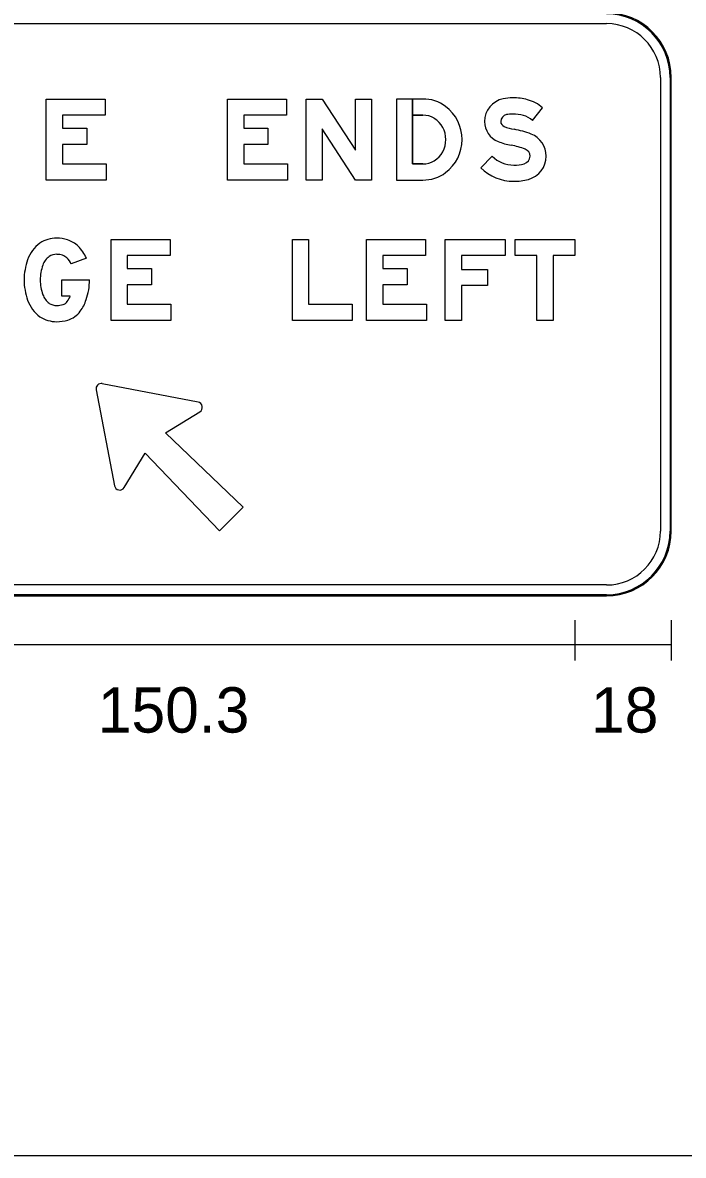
# Model space of a CAD drawing. Extents: x 10268147 to 10268469, y 2141099 to 2141204.
# Drawn here: x 10268201.56 to 10268211.77, y 2141130.4 to 2141147.88 of the extents above; entities that cross this region are included whole.
import ezdxf

# ---------------------------------------------------------------- set-up
doc = ezdxf.new("R2010")
doc.units = 0
for name, color, linetype in [('61', 7, 'Continuous'), ('GSDims', 7, 'Continuous'), ('PlotBorder_dp', 7, 'Continuous')]:
    doc.layers.add(name, color=color, linetype=linetype)

msp = doc.modelspace()

# ---------------------------------------------------------------- linework, layer by layer
at = {"layer": '61'}
msp.add_line((10268153.875, 2141130.399), (10268229.209, 2141130.399), dxfattribs=at)
at = {"layer": 'GSDims'}
for p, q in [((10268210.093, 2141138.662), (10268210.093, 2141138.037)), ((10268210.093, 2141138.662), (10268210.093, 2141138.037)), ((10268211.581, 2141138.662), (10268211.581, 2141138.037)), ((10268197.568, 2141138.287), (10268210.093, 2141138.287)), ((10268210.093, 2141138.287), (10268211.581, 2141138.287))]:
    msp.add_line(p, q, dxfattribs=at)
at = {"layer": 'PlotBorder_dp'}
for p, q in [((10268197.081, 2141147.87), (10268210.581, 2141147.87)), ((10268197.081, 2141147.87), (10268210.581, 2141147.87)), ((10268211.414, 2141147.037), (10268211.414, 2141140.037)), ((10268211.414, 2141147.037), (10268211.414, 2141140.037)), ((10268211.564, 2141147.037), (10268211.564, 2141140.037)), ((10268211.581, 2141140.037), (10268211.581, 2141147.037)), ((10268211.581, 2141140.037), (10268211.581, 2141147.037)), ((10268211.581, 2141140.037), (10268211.581, 2141147.037)), ((10268211.581, 2141140.037), (10268211.581, 2141147.037)), ((10268207.745, 2141145.705), (10268207.585, 2141145.705)), ((10268207.745, 2141145.705), (10268207.585, 2141145.705)), ((10268207.745, 2141145.705), (10268207.745, 2141145.705)), ((10268207.745, 2141145.455), (10268207.745, 2141145.455)), ((10268204.272, 2141142.027), (10268202.792, 2141142.311)), ((10268204.272, 2141142.027), (10268202.792, 2141142.311)), ((10268204.272, 2141142.027), (10268202.792, 2141142.311)), ((10268202.696, 2141142.215), (10268202.981, 2141140.736)), ((10268202.696, 2141142.215), (10268202.981, 2141140.736)), ((10268202.696, 2141142.215), (10268202.981, 2141140.736)), ((10268202.981, 2141140.736), (10268202.981, 2141140.736)), ((10268202.981, 2141140.736), (10268202.981, 2141140.736)), ((10268202.981, 2141140.736), (10268202.981, 2141140.736)), ((10268210.581, 2141139.204), (10268197.082, 2141139.204)), ((10268210.581, 2141139.204), (10268197.082, 2141139.204)), ((10268210.581, 2141139.054), (10268197.081, 2141139.054)), ((10268197.081, 2141139.037), (10268210.581, 2141139.037)), ((10268197.081, 2141139.037), (10268210.581, 2141139.037)), ((10268197.082, 2141139.037), (10268210.581, 2141139.037)), ((10268197.082, 2141139.037), (10268210.581, 2141139.037))]:
    msp.add_line(p, q, dxfattribs=at)
for points in [[(10268202.838, 2141146.705), (10268202.838, 2141146.455), (10268202.176, 2141146.455), (10268202.176, 2141146.255), (10268202.551, 2141146.255), (10268202.551, 2141146.005), (10268202.176, 2141146.005), (10268202.176, 2141145.705), (10268202.851, 2141145.705), (10268202.851, 2141145.455), (10268201.926, 2141145.455), (10268201.926, 2141146.705)], [(10268202.838, 2141146.705), (10268202.838, 2141146.455), (10268202.176, 2141146.455), (10268202.176, 2141146.255), (10268202.551, 2141146.255), (10268202.551, 2141146.005), (10268202.176, 2141146.005), (10268202.176, 2141145.705), (10268202.851, 2141145.705), (10268202.851, 2141145.455), (10268201.926, 2141145.455), (10268201.926, 2141146.705)], [(10268202.838, 2141146.705), (10268202.838, 2141146.455), (10268202.176, 2141146.455), (10268202.176, 2141146.255), (10268202.551, 2141146.255), (10268202.551, 2141146.005), (10268202.176, 2141146.005), (10268202.176, 2141145.705), (10268202.851, 2141145.705), (10268202.851, 2141145.455), (10268201.926, 2141145.455), (10268201.926, 2141146.705)], [(10268205.638, 2141146.705), (10268205.638, 2141146.455), (10268204.976, 2141146.455), (10268204.976, 2141146.255), (10268205.351, 2141146.255), (10268205.351, 2141146.005), (10268204.976, 2141146.005), (10268204.976, 2141145.705), (10268205.651, 2141145.705), (10268205.651, 2141145.455), (10268204.726, 2141145.455), (10268204.726, 2141146.705)], [(10268205.638, 2141146.705), (10268205.638, 2141146.455), (10268204.976, 2141146.455), (10268204.976, 2141146.255), (10268205.351, 2141146.255), (10268205.351, 2141146.005), (10268204.976, 2141146.005), (10268204.976, 2141145.705), (10268205.651, 2141145.705), (10268205.651, 2141145.455), (10268204.726, 2141145.455), (10268204.726, 2141146.705)], [(10268205.638, 2141146.705), (10268205.638, 2141146.455), (10268204.976, 2141146.455), (10268204.976, 2141146.255), (10268205.351, 2141146.255), (10268205.351, 2141146.005), (10268204.976, 2141146.005), (10268204.976, 2141145.705), (10268205.651, 2141145.705), (10268205.651, 2141145.455), (10268204.726, 2141145.455), (10268204.726, 2141146.705)], [(10268205.939, 2141146.705), (10268206.189, 2141146.705), (10268206.702, 2141145.917), (10268206.702, 2141146.705), (10268206.952, 2141146.705), (10268206.952, 2141145.455), (10268206.705, 2141145.455), (10268206.189, 2141146.246), (10268206.189, 2141145.455), (10268205.939, 2141145.455)], [(10268205.939, 2141146.705), (10268206.189, 2141146.705), (10268206.702, 2141145.917), (10268206.702, 2141146.705), (10268206.952, 2141146.705), (10268206.952, 2141145.455), (10268206.705, 2141145.455), (10268206.189, 2141146.246), (10268206.189, 2141145.455), (10268205.939, 2141145.455)], [(10268205.939, 2141146.705), (10268206.189, 2141146.705), (10268206.702, 2141145.917), (10268206.702, 2141146.705), (10268206.952, 2141146.705), (10268206.952, 2141145.455), (10268206.705, 2141145.455), (10268206.189, 2141146.246), (10268206.189, 2141145.455), (10268205.939, 2141145.455)], [(10268203.84, 2141144.538), (10268203.84, 2141144.288), (10268203.178, 2141144.288), (10268203.178, 2141144.088), (10268203.553, 2141144.088), (10268203.553, 2141143.838), (10268203.178, 2141143.838), (10268203.178, 2141143.538), (10268203.853, 2141143.538), (10268203.853, 2141143.288), (10268202.928, 2141143.288), (10268202.928, 2141144.538)], [(10268203.84, 2141144.538), (10268203.84, 2141144.288), (10268203.178, 2141144.288), (10268203.178, 2141144.088), (10268203.553, 2141144.088), (10268203.553, 2141143.838), (10268203.178, 2141143.838), (10268203.178, 2141143.538), (10268203.853, 2141143.538), (10268203.853, 2141143.288), (10268202.928, 2141143.288), (10268202.928, 2141144.538)], [(10268203.84, 2141144.538), (10268203.84, 2141144.288), (10268203.178, 2141144.288), (10268203.178, 2141144.088), (10268203.553, 2141144.088), (10268203.553, 2141143.838), (10268203.178, 2141143.838), (10268203.178, 2141143.538), (10268203.853, 2141143.538), (10268203.853, 2141143.288), (10268202.928, 2141143.288), (10268202.928, 2141144.538)], [(10268205.978, 2141143.538), (10268206.653, 2141143.538), (10268206.653, 2141143.288), (10268205.728, 2141143.288), (10268205.728, 2141144.538), (10268205.978, 2141144.538)], [(10268205.978, 2141143.538), (10268206.653, 2141143.538), (10268206.653, 2141143.288), (10268205.728, 2141143.288), (10268205.728, 2141144.538), (10268205.978, 2141144.538)], [(10268205.978, 2141143.538), (10268206.653, 2141143.538), (10268206.653, 2141143.288), (10268205.728, 2141143.288), (10268205.728, 2141144.538), (10268205.978, 2141144.538)], [(10268207.787, 2141144.538), (10268207.787, 2141144.288), (10268207.125, 2141144.288), (10268207.125, 2141144.088), (10268207.5, 2141144.088), (10268207.5, 2141143.838), (10268207.125, 2141143.838), (10268207.125, 2141143.538), (10268207.8, 2141143.538), (10268207.8, 2141143.288), (10268206.875, 2141143.288), (10268206.875, 2141144.538)], [(10268207.787, 2141144.538), (10268207.787, 2141144.288), (10268207.125, 2141144.288), (10268207.125, 2141144.088), (10268207.5, 2141144.088), (10268207.5, 2141143.838), (10268207.125, 2141143.838), (10268207.125, 2141143.538), (10268207.8, 2141143.538), (10268207.8, 2141143.288), (10268206.875, 2141143.288), (10268206.875, 2141144.538)], [(10268207.787, 2141144.538), (10268207.787, 2141144.288), (10268207.125, 2141144.288), (10268207.125, 2141144.088), (10268207.5, 2141144.088), (10268207.5, 2141143.838), (10268207.125, 2141143.838), (10268207.125, 2141143.538), (10268207.8, 2141143.538), (10268207.8, 2141143.288), (10268206.875, 2141143.288), (10268206.875, 2141144.538)], [(10268208.091, 2141144.538), (10268209.016, 2141144.538), (10268209.016, 2141144.288), (10268208.341, 2141144.288), (10268208.341, 2141144.075), (10268208.741, 2141144.075), (10268208.741, 2141143.825), (10268208.341, 2141143.825), (10268208.341, 2141143.288), (10268208.091, 2141143.288)], [(10268208.091, 2141144.538), (10268209.016, 2141144.538), (10268209.016, 2141144.288), (10268208.341, 2141144.288), (10268208.341, 2141144.075), (10268208.741, 2141144.075), (10268208.741, 2141143.825), (10268208.341, 2141143.825), (10268208.341, 2141143.288), (10268208.091, 2141143.288)], [(10268208.091, 2141144.538), (10268209.016, 2141144.538), (10268209.016, 2141144.288), (10268208.341, 2141144.288), (10268208.341, 2141144.075), (10268208.741, 2141144.075), (10268208.741, 2141143.825), (10268208.341, 2141143.825), (10268208.341, 2141143.288), (10268208.091, 2141143.288)], [(10268209.756, 2141143.288), (10268209.506, 2141143.288), (10268209.506, 2141144.288), (10268209.168, 2141144.288), (10268209.168, 2141144.538), (10268210.093, 2141144.538), (10268210.093, 2141144.288), (10268209.756, 2141144.288)], [(10268209.756, 2141143.288), (10268209.506, 2141143.288), (10268209.506, 2141144.288), (10268209.168, 2141144.288), (10268209.168, 2141144.538), (10268210.093, 2141144.538), (10268210.093, 2141144.288), (10268209.756, 2141144.288)], [(10268209.756, 2141143.288), (10268209.506, 2141143.288), (10268209.506, 2141144.288), (10268209.168, 2141144.288), (10268209.168, 2141144.538), (10268210.093, 2141144.538), (10268210.093, 2141144.288), (10268209.756, 2141144.288)]]:
    msp.add_lwpolyline(points, close=True, dxfattribs=at)
for points in [[(10268207.745, 2141146.705), (10268207.337, 2141146.705), (10268207.337, 2141145.455), (10268207.745, 2141145.455)], [(10268207.585, 2141145.705), (10268207.585, 2141146.705), (10268207.337, 2141146.705), (10268207.337, 2141145.455), (10268207.745, 2141145.455)], [(10268207.585, 2141145.705), (10268207.585, 2141146.705), (10268207.337, 2141146.705), (10268207.337, 2141145.455), (10268207.745, 2141145.455)], [(10268207.745, 2141146.705), (10268207.585, 2141146.705), (10268207.585, 2141146.455), (10268207.745, 2141146.455)], [(10268207.745, 2141146.705), (10268207.585, 2141146.705), (10268207.585, 2141146.455), (10268207.745, 2141146.455)], [(10268209.438, 2141146.375), (10268209.593, 2141146.572)], [(10268209.438, 2141146.375), (10268209.593, 2141146.572)], [(10268209.438, 2141146.375), (10268209.593, 2141146.572)], [(10268207.745, 2141146.455), (10268207.585, 2141146.455), (10268207.585, 2141145.705), (10268207.745, 2141145.705)], [(10268208.814, 2141145.822), (10268208.638, 2141145.645)], [(10268208.814, 2141145.822), (10268208.638, 2141145.645)], [(10268208.814, 2141145.822), (10268208.638, 2141145.645)], [(10268202.546, 2141144.248), (10268202.312, 2141144.159)], [(10268202.546, 2141144.248), (10268202.312, 2141144.159)], [(10268202.546, 2141144.248), (10268202.312, 2141144.159)], [(10268202.298, 2141143.663), (10268202.168, 2141143.663), (10268202.168, 2141143.913), (10268202.595, 2141143.913)], [(10268202.298, 2141143.663), (10268202.168, 2141143.663), (10268202.168, 2141143.913), (10268202.595, 2141143.913)], [(10268202.298, 2141143.663), (10268202.168, 2141143.663), (10268202.168, 2141143.913), (10268202.595, 2141143.913)], [(10268203.131, 2141140.708), (10268203.456, 2141141.239), (10268204.602, 2141140.041), (10268204.966, 2141140.405), (10268203.769, 2141141.552), (10268204.299, 2141141.876)], [(10268203.131, 2141140.708), (10268203.456, 2141141.239), (10268204.602, 2141140.041), (10268204.966, 2141140.405), (10268203.769, 2141141.552), (10268204.299, 2141141.876)], [(10268203.131, 2141140.708), (10268203.456, 2141141.239), (10268204.602, 2141140.041), (10268204.966, 2141140.405), (10268203.769, 2141141.552), (10268204.299, 2141141.876)]]:
    msp.add_lwpolyline(points, dxfattribs=at)
for centre, radius, start, end in [((10268210.581, 2141147.037), 1, 0, 90), ((10268210.581, 2141147.037), 1, 0, 90), ((10268210.581, 2141147.037), 1, 0, 90), ((10268210.581, 2141147.037), 1, 0, 90), ((10268210.581, 2141147.037), 0.983, 0, 90), ((10268210.581, 2141147.037), 0.833, 0, 90), ((10268210.581, 2141147.037), 0.833, 0, 90), ((10268202.777, 2141142.231), 0.082, 79.1228, 190.8772), ((10268202.777, 2141142.231), 0.082, 79.1228, 190.8772), ((10268202.777, 2141142.231), 0.082, 79.1228, 190.8772), ((10268204.256, 2141141.946), 0.082, 301.4719, 79.1228), ((10268204.256, 2141141.946), 0.082, 301.4719, 79.1228), ((10268204.256, 2141141.946), 0.082, 301.4719, 79.1228), ((10268203.061, 2141140.751), 0.082, 190.8772, 328.5281), ((10268203.061, 2141140.751), 0.082, 190.8772, 328.5281), ((10268203.061, 2141140.751), 0.082, 190.8772, 328.5281), ((10268210.581, 2141140.037), 1, 270, 0), ((10268210.581, 2141140.037), 1, 270, 0), ((10268210.581, 2141140.037), 0.833, 270, 0), ((10268210.581, 2141140.037), 1, 270, 0), ((10268210.581, 2141140.037), 0.833, 270, 0), ((10268210.581, 2141140.037), 1, 270, 0), ((10268210.581, 2141140.037), 0.983, 270, 0)]:
    msp.add_arc(centre, radius, start, end, dxfattribs=at)
for centre, major_axis, ratio, start_param, end_param in [((10268207.761, 2141146.158), (0, 0.547), 0.992004, 5.621793, 6.313477), ((10268207.761, 2141146.158), (0, 0.547), 0.992004, 5.621793, 6.313477), ((10268207.761, 2141146.158), (0, 0.547), 0.992004, 5.621793, 6.313477), ((10268209.056, 2141146.359), (0, 0.358), 0.999995, 0.202758, 1.570796), ((10268209.056, 2141146.359), (0, 0.358), 0.999995, 0.202758, 1.570796), ((10268209.056, 2141146.359), (0, 0.358), 0.999995, 0.202758, 1.570796), ((10268209.132, 2141145.988), (0, 0.736), 0.999995, 0, 0.202758), ((10268209.132, 2141145.988), (0, 0.736), 0.999995, 0, 0.202758), ((10268209.132, 2141145.988), (0, 0.736), 0.999995, 0, 0.202758), ((10268209.132, 2141145.821), (0, 0.903), 0.999995, 6.026234, 6.283185), ((10268209.132, 2141145.821), (0, 0.903), 0.999995, 6.026234, 6.283185), ((10268209.132, 2141145.821), (0, 0.903), 0.999995, 6.026234, 6.283185), ((10268209.216, 2141146.14), (0, 0.573), 0.999995, 5.565152, 6.026234), ((10268209.216, 2141146.14), (0, 0.573), 0.999995, 5.565152, 6.026234), ((10268209.216, 2141146.14), (0, 0.573), 0.999995, 5.565152, 6.026234), ((10268207.732, 2141146.086), (0, 0.622), 0.992004, 4.702399, 5.655315), ((10268207.732, 2141146.086), (0, 0.622), 0.992004, 4.702399, 5.655315), ((10268207.732, 2141146.086), (0, 0.622), 0.992004, 4.702399, 5.655315), ((10268209.132, 2141145.988), (0, 0.486), 0.999995, 0, 0.202758), ((10268209.132, 2141145.988), (0, 0.486), 0.999995, 0, 0.202758), ((10268209.132, 2141145.988), (0, 0.486), 0.999995, 0, 0.202758), ((10268209.132, 2141145.821), (0, 0.653), 0.999995, 6.026234, 6.283185), ((10268209.132, 2141145.821), (0, 0.653), 0.999995, 6.026234, 6.283185), ((10268209.132, 2141145.821), (0, 0.653), 0.999995, 6.026234, 6.283185), ((10268207.751, 2141146.117), (0, 0.338), 0.992004, 5.75224, 6.301036), ((10268207.751, 2141146.117), (0, 0.338), 0.992004, 5.75224, 6.301036), ((10268207.751, 2141146.117), (0, 0.338), 0.992004, 5.75224, 6.301036), ((10268207.728, 2141146.089), (0, 0.373), 0.992004, 4.686283, 5.735161), ((10268207.728, 2141146.089), (0, 0.373), 0.992004, 4.686283, 5.735161), ((10268207.728, 2141146.089), (0, 0.373), 0.992004, 4.686283, 5.735161), ((10268209.029, 2141146.359), (0, 0.332), 0.999995, 1.570796, 2.761249), ((10268209.029, 2141146.359), (0, 0.332), 0.999995, 1.570796, 2.761249), ((10268209.029, 2141146.359), (0, 0.332), 0.999995, 1.570796, 2.761249), ((10268209.056, 2141146.359), (0, 0.108), 0.999995, 0.202758, 1.570796), ((10268209.056, 2141146.359), (0, 0.108), 0.999995, 0.202758, 1.570796), ((10268209.056, 2141146.359), (0, 0.108), 0.999995, 0.202758, 1.570796), ((10268209.029, 2141146.359), (0, 0.0817), 0.999995, 1.570796, 2.761249), ((10268209.029, 2141146.359), (0, 0.0817), 0.999995, 1.570796, 2.761249), ((10268209.029, 2141146.359), (0, 0.0817), 0.999995, 1.570796, 2.761249), ((10268209.216, 2141146.14), (0, 0.323), 0.999995, 5.523837, 6.026234), ((10268209.216, 2141146.14), (0, 0.323), 0.999995, 5.523837, 6.026234), ((10268209.216, 2141146.14), (0, 0.323), 0.999995, 5.523837, 6.026234), ((10268209.302, 2141147.04), (0, 0.816), 0.999995, 2.761249, 2.95744), ((10268209.302, 2141147.04), (0, 0.816), 0.999995, 2.761249, 2.95744), ((10268209.302, 2141147.04), (0, 0.816), 0.999995, 2.761249, 2.95744), ((10268208.874, 2141144.742), (0, 1.522), 0.999995, 5.918637, 6.099033), ((10268208.874, 2141144.742), (0, 1.522), 0.999995, 5.918637, 6.099033), ((10268208.874, 2141144.742), (0, 1.522), 0.999995, 5.918637, 6.099033), ((10268209.286, 2141145.824), (0, 0.364), 0.999995, 4.712389, 5.918637), ((10268209.286, 2141145.824), (0, 0.364), 0.999995, 4.712389, 5.918637), ((10268209.286, 2141145.824), (0, 0.364), 0.999995, 4.712389, 5.918637), ((10268207.728, 2141146.07), (0, 0.373), 0.992004, 3.689617, 4.738495), ((10268207.728, 2141146.07), (0, 0.373), 0.992004, 3.689617, 4.738495), ((10268207.728, 2141146.07), (0, 0.373), 0.992004, 3.689617, 4.738495), ((10268207.732, 2141146.074), (0, 0.622), 0.992004, 3.769463, 4.722379), ((10268207.732, 2141146.074), (0, 0.622), 0.992004, 3.769463, 4.722379), ((10268207.732, 2141146.074), (0, 0.622), 0.992004, 3.769463, 4.722379), ((10268209.302, 2141147.04), (0, 1.066), 0.999995, 2.761249, 2.95744), ((10268209.302, 2141147.04), (0, 1.066), 0.999995, 2.761249, 2.95744), ((10268209.302, 2141147.04), (0, 1.066), 0.999995, 2.761249, 2.95744), ((10268208.874, 2141144.742), (0, 1.272), 0.999995, 5.918637, 6.099033), ((10268208.874, 2141144.742), (0, 1.272), 0.999995, 5.918637, 6.099033), ((10268208.874, 2141144.742), (0, 1.272), 0.999995, 5.918637, 6.099033), ((10268209.147, 2141146.158), (0, 0.473), 0.999995, 2.360607, 3.141593), ((10268209.147, 2141146.158), (0, 0.473), 0.999995, 2.360607, 3.141593), ((10268209.147, 2141146.158), (0, 0.473), 0.999995, 2.360607, 3.141593), ((10268209.279, 2141145.824), (0, 0.121), 0.999995, 3.401517, 4.712389), ((10268209.279, 2141145.824), (0, 0.121), 0.999995, 3.401517, 4.712389), ((10268209.279, 2141145.824), (0, 0.121), 0.999995, 3.401517, 4.712389), ((10268209.286, 2141145.824), (0, 0.114), 0.999995, 4.712389, 5.918637), ((10268209.286, 2141145.824), (0, 0.114), 0.999995, 4.712389, 5.918637), ((10268209.286, 2141145.824), (0, 0.114), 0.999995, 4.712389, 5.918637), ((10268209.279, 2141145.824), (0, 0.371), 0.999995, 3.401517, 4.712389), ((10268209.279, 2141145.824), (0, 0.371), 0.999995, 3.401517, 4.712389), ((10268209.279, 2141145.824), (0, 0.371), 0.999995, 3.401517, 4.712389), ((10268207.751, 2141146.043), (0, 0.338), 0.992004, 3.123742, 3.672538), ((10268207.751, 2141146.043), (0, 0.338), 0.992004, 3.123742, 3.672538), ((10268207.751, 2141146.043), (0, 0.338), 0.992004, 3.123742, 3.672538), ((10268209.147, 2141146.158), (0, 0.723), 0.999995, 2.360607, 3.141593), ((10268209.147, 2141146.158), (0, 0.723), 0.999995, 2.360607, 3.141593), ((10268209.147, 2141146.158), (0, 0.723), 0.999995, 2.360607, 3.141593), ((10268209.147, 2141146.321), (0, 0.636), 0.999995, 3.141593, 3.401517), ((10268209.147, 2141146.321), (0, 0.636), 0.999995, 3.141593, 3.401517), ((10268209.147, 2141146.321), (0, 0.636), 0.999995, 3.141593, 3.401517), ((10268207.761, 2141146.002), (0, 0.547), 0.992004, 3.111301, 3.802985), ((10268207.761, 2141146.002), (0, 0.547), 0.992004, 3.111301, 3.802985), ((10268207.761, 2141146.002), (0, 0.547), 0.992004, 3.111301, 3.802985), ((10268209.147, 2141146.321), (0, 0.886), 0.999995, 3.141593, 3.401517), ((10268209.147, 2141146.321), (0, 0.886), 0.999995, 3.141593, 3.401517), ((10268209.147, 2141146.321), (0, 0.886), 0.999995, 3.141593, 3.401517), ((10268202.089, 2141144.079), (0, 0.479), 0.999997, 6.282946, 6.85835), ((10268202.089, 2141144.079), (0, 0.479), 0.999997, 6.282946, 6.85835), ((10268202.089, 2141144.079), (0, 0.479), 0.999997, 6.282946, 6.85835), ((10268202.089, 2141144.02), (0, 0.537), 0.999997, 5.968128, 6.283185), ((10268202.089, 2141144.02), (0, 0.537), 0.999997, 5.968128, 6.283185), ((10268202.089, 2141144.02), (0, 0.537), 0.999997, 5.968128, 6.283185), ((10268202.151, 2141144.042), (0, 0.545), 0.999997, 0.634329, 1.227998), ((10268202.151, 2141144.042), (0, 0.545), 0.999997, 0.634329, 1.227998), ((10268202.151, 2141144.042), (0, 0.545), 0.999997, 0.634329, 1.227998), ((10268202.124, 2141144.127), (0, 0.425), 0.999997, 5.51497, 5.968128), ((10268202.124, 2141144.127), (0, 0.425), 0.999997, 5.51497, 5.968128), ((10268202.124, 2141144.127), (0, 0.425), 0.999997, 5.51497, 5.968128), ((10268202.031, 2141144.03), (0, 0.559), 0.999997, 5.112302, 5.51497), ((10268202.031, 2141144.03), (0, 0.559), 0.999997, 5.112302, 5.51497), ((10268202.031, 2141144.03), (0, 0.559), 0.999997, 5.112302, 5.51497), ((10268202.571, 2141143.898), (0, 0.988), 0.999997, 1.233536, 1.555728), ((10268202.571, 2141143.898), (0, 0.988), 0.999997, 1.233536, 1.555728), ((10268202.571, 2141143.898), (0, 0.988), 0.999997, 1.233536, 1.555728), ((10268202.151, 2141144.042), (0, 0.295), 0.999997, 0.660238, 1.227998), ((10268202.151, 2141144.042), (0, 0.295), 0.999997, 0.660238, 1.227998), ((10268202.151, 2141144.042), (0, 0.295), 0.999997, 0.660238, 1.227998), ((10268202.089, 2141144.079), (0, 0.229), 0.999997, 6.282815, 6.826868), ((10268202.089, 2141144.079), (0, 0.229), 0.999997, 6.282815, 6.826868), ((10268202.089, 2141144.079), (0, 0.229), 0.999997, 6.282815, 6.826868), ((10268202.089, 2141144.02), (0, 0.287), 0.999997, 5.968128, 6.283185), ((10268202.089, 2141144.02), (0, 0.287), 0.999997, 5.968128, 6.283185), ((10268202.089, 2141144.02), (0, 0.287), 0.999997, 5.968128, 6.283185), ((10268202.124, 2141144.127), (0, 0.175), 0.999997, 5.51497, 5.968128), ((10268202.124, 2141144.127), (0, 0.175), 0.999997, 5.51497, 5.968128), ((10268202.124, 2141144.127), (0, 0.175), 0.999997, 5.51497, 5.968128), ((10268202.031, 2141144.03), (0, 0.309), 0.999997, 5.141395, 5.51497), ((10268202.031, 2141144.03), (0, 0.309), 0.999997, 5.141395, 5.51497), ((10268202.031, 2141144.03), (0, 0.309), 0.999997, 5.141395, 5.51497), ((10268202.515, 2141143.912), (0, 0.681), 0.999997, 1.228714, 1.570494), ((10268202.515, 2141143.912), (0, 0.681), 0.999997, 1.228714, 1.570494), ((10268202.515, 2141143.912), (0, 0.681), 0.999997, 1.228714, 1.570494), ((10268202.571, 2141143.928), (0, 0.988), 0.999997, 1.585865, 1.908057), ((10268202.571, 2141143.928), (0, 0.988), 0.999997, 1.585865, 1.908057), ((10268202.571, 2141143.928), (0, 0.988), 0.999997, 1.585865, 1.908057), ((10268202.515, 2141143.913), (0, 0.681), 0.999997, 1.571362, 1.913142), ((10268202.515, 2141143.913), (0, 0.681), 0.999997, 1.571362, 1.913142), ((10268202.515, 2141143.913), (0, 0.681), 0.999997, 1.571362, 1.913142), ((10268201.68, 2141143.913), (0, 0.915), 0.999997, 4.373891, 4.712389), ((10268201.68, 2141143.913), (0, 0.915), 0.999997, 4.373891, 4.712389), ((10268201.68, 2141143.913), (0, 0.915), 0.999997, 4.373891, 4.712389), ((10268202.151, 2141143.784), (0, 0.294), 0.999997, 1.913852, 2.481612), ((10268202.151, 2141143.784), (0, 0.294), 0.999997, 1.913852, 2.481612), ((10268202.151, 2141143.784), (0, 0.294), 0.999997, 1.913852, 2.481612), ((10268202.151, 2141143.784), (0, 0.545), 0.999997, 1.913595, 2.507264), ((10268202.151, 2141143.784), (0, 0.545), 0.999997, 1.913595, 2.507264), ((10268202.151, 2141143.784), (0, 0.545), 0.999997, 1.913595, 2.507264), ((10268202.089, 2141143.747), (0, 0.229), 0.999997, 2.597779, 3.141832), ((10268202.089, 2141143.747), (0, 0.229), 0.999997, 2.597779, 3.141832), ((10268202.089, 2141143.747), (0, 0.229), 0.999997, 2.597779, 3.141832), ((10268202.089, 2141143.852), (0, 0.334), 0.999997, 3.141503, 3.435382), ((10268202.089, 2141143.852), (0, 0.334), 0.999997, 3.141503, 3.435382), ((10268202.089, 2141143.852), (0, 0.334), 0.999997, 3.141503, 3.435382), ((10268202.148, 2141143.656), (0, 0.129), 0.999997, 3.435472, 4.071542), ((10268202.148, 2141143.656), (0, 0.129), 0.999997, 3.435472, 4.071542), ((10268202.148, 2141143.656), (0, 0.129), 0.999997, 3.435472, 4.071542), ((10268201.979, 2141143.782), (0, 0.34), 0.999997, 4.071542, 4.353904), ((10268201.979, 2141143.782), (0, 0.34), 0.999997, 4.071542, 4.353904), ((10268201.979, 2141143.782), (0, 0.34), 0.999997, 4.071542, 4.353904), ((10268201.979, 2141143.782), (0, 0.59), 0.999997, 4.071542, 4.414751), ((10268201.979, 2141143.782), (0, 0.59), 0.999997, 4.071542, 4.414751), ((10268201.979, 2141143.782), (0, 0.59), 0.999997, 4.071542, 4.414751), ((10268202.089, 2141143.747), (0, 0.479), 0.999997, 2.566428, 3.141832), ((10268202.089, 2141143.747), (0, 0.479), 0.999997, 2.566428, 3.141832), ((10268202.089, 2141143.747), (0, 0.479), 0.999997, 2.566428, 3.141832), ((10268202.148, 2141143.656), (0, 0.379), 0.999997, 3.435472, 4.071542), ((10268202.148, 2141143.656), (0, 0.379), 0.999997, 3.435472, 4.071542), ((10268202.148, 2141143.656), (0, 0.379), 0.999997, 3.435472, 4.071542), ((10268202.089, 2141143.852), (0, 0.584), 0.999997, 3.141593, 3.435472), ((10268202.089, 2141143.852), (0, 0.584), 0.999997, 3.141593, 3.435472), ((10268202.089, 2141143.852), (0, 0.584), 0.999997, 3.141593, 3.435472)]:
    msp.add_ellipse(centre, major_axis=major_axis, ratio=ratio, start_param=start_param, end_param=end_param, dxfattribs=at)

# ---------------------------------------------------------------- texts
at = {"layer": 'GSDims'}
for s, p in [('150.3', (10268202.722, 2141136.925)), ('18', (10268210.341, 2141136.925))]:
    msp.add_text(s, height=0.7, dxfattribs=at).set_placement(p)

doc.saveas('drawing.dxf')
